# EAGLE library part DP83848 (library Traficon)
DP83848C PHYTER® - Commercial Temperature Single Port 10/100 Mb/s Ethernet Physical Layer Transceiver
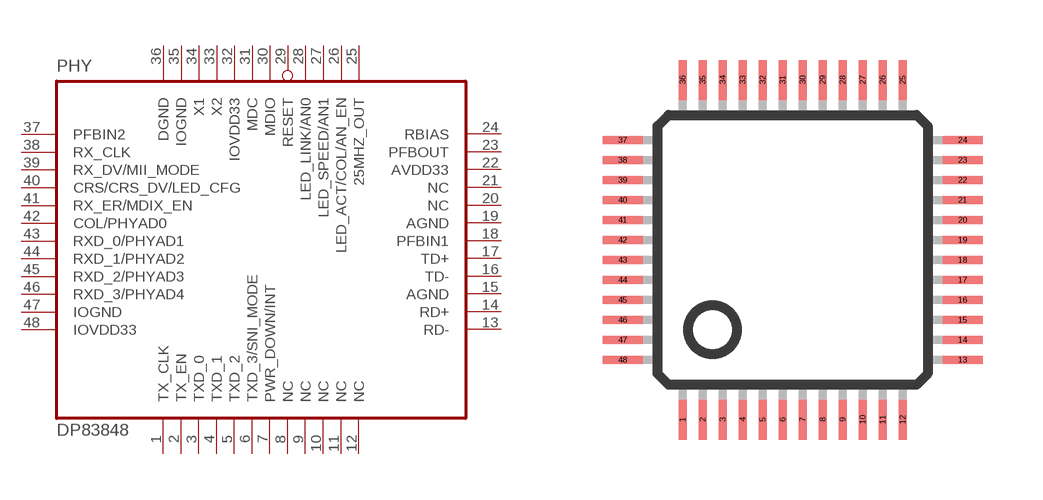
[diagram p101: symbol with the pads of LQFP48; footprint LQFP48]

Designator prefix PHY

## DP83848C  [LQFP48]
1  TX_CLK
2  TX_EN
3  TXD_0
4  TXD_1
5  TXD_2
6  TXD_3/SNI_MODE
7  PWR_DOWN/INT
8  NC
9  NC
10  NC
11  NC
12  NC
13  RD-
14  RD+
15  AGND
16  TD-
17  TD+
18  PFBIN1
19  AGND
20  NC
21  NC
22  AVDD33
23  PFBOUT
24  RBIAS
25  25MHZ_OUT
26  LED_ACT/COL/AN_EN
27  LED_SPEED/AN1
28  LED_LINK/AN0
29  RESET
30  MDIO
31  MDC
32  IOVDD33
33  X2
34  X1
35  IOGND
36  DGND
37  PFBIN2
38  RX_CLK
39  RX_DV/MII_MODE
40  CRS/CRS_DV/LED_CFG
41  RX_ER/MDIX_EN
42  COL/PHYAD0
43  RXD_0/PHYAD1
44  RXD_1/PHYAD2
45  RXD_2/PHYAD3
46  RXD_3/PHYAD4
47  IOGND
48  IOVDD33

## Footprint LQFP48 (pad centres in mm)
48-pin plastic LQFP (FPT-48P-M26) www.fma.fujitsu.com/pdf/e713717.pdf
smd 0.2 x 1: 1 -2.75,-4.25; 2 -2.25,-4.25; 3 -1.75,-4.25; 4 -1.25,-4.25; 5 -0.75,-4.25; 6 -0.25,-4.25; 7 0.25,-4.25; 8 0.75,-4.25; 9 1.25,-4.25; 10 1.75,-4.25; 11 2.25,-4.25; 12 2.75,-4.25; 25 2.75,4.25; 26 2.25,4.25; 27 1.75,4.25; 28 1.25,4.25; 29 0.75,4.25; 30 0.25,4.25; 31 -0.25,4.25; 32 -0.75,4.25; 33 -1.25,4.25; 34 -1.75,4.25; 35 -2.25,4.25; 36 -2.75,4.25
smd 1 x 0.2: 13 4.25,-2.75; 14 4.25,-2.25; 15 4.25,-1.75; 16 4.25,-1.25; 17 4.25,-0.75; 18 4.25,-0.25; 19 4.25,0.25; 20 4.25,0.75; 21 4.25,1.25; 22 4.25,1.75; 23 4.25,2.25; 24 4.25,2.75; 37 -4.25,2.75; 38 -4.25,2.25; 39 -4.25,1.75; 40 -4.25,1.25; 41 -4.25,0.75; 42 -4.25,0.25; 43 -4.25,-0.25; 44 -4.25,-0.75; 45 -4.25,-1.25; 46 -4.25,-1.75; 47 -4.25,-2.25; 48 -4.25,-2.75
